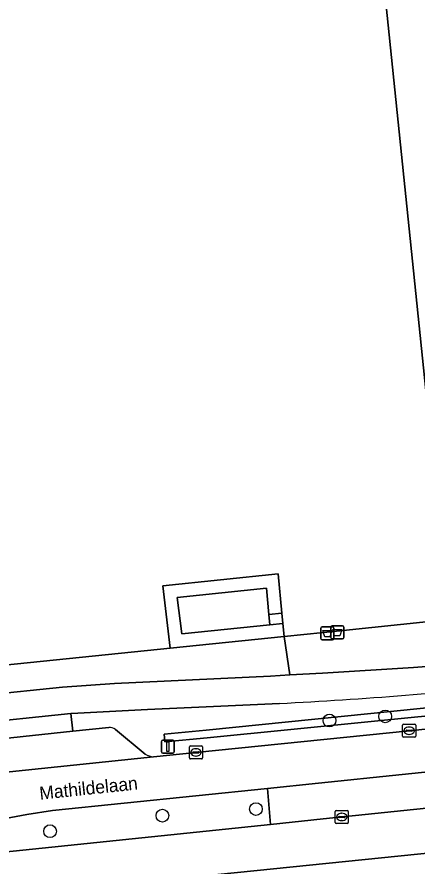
# Model space of a CAD drawing. Extents: x 160675 to 161153, y 383241 to 383714.
# Drawn here: x 161064.7 to 161095.4, y 383570 to 383635.2 of the extents above; entities that cross this region are included whole.
import ezdxf

# ---------------------------------------------------------------- set-up
doc = ezdxf.new("R2010")
doc.units = 0
for name, color, linetype in [('IMGEO_Afvalbak', 7, 'Continuous'), ('IMGEO_Berm_groen', 7, 'Continuous'), ('IMGEO_Boom', 7, 'Continuous'), ('IMGEO_Fietspad_gesloten', 7, 'Continuous'), ('IMGEO_Groenvoorziening', 7, 'Continuous'), ('IMGEO_Haag', 7, 'Continuous'), ('IMGEO_Kolk', 7, 'Continuous'), ('IMGEO_Lichtmast', 7, 'Continuous'), ('IMGEO_Openbare_ruimte_label', 7, 'Continuous'), ('IMGEO_OVBaan_gesloten', 7, 'Continuous'), ('IMGEO_Pand', 7, 'Continuous'), ('IMGEO_Parkeervlak_open', 7, 'Continuous'), ('IMGEO_Rijbaan_lokaal_gesloten', 7, 'Continuous'), ('IMGEO_Voetpad_open', 7, 'Continuous')]:
    doc.layers.add(name, color=color, linetype=linetype)

msp = doc.modelspace()

# ---------------------------------------------------------------- linework, layer by layer
at = {"layer": 'IMGEO_Afvalbak'}
for p, q in [((161088.02, 383587.528), (161088.02, 383588.328)), ((161088.02, 383588.328), (161088.02, 383587.528)), ((161088.12, 383588.428), (161088.91, 383588.428)), ((161088.91, 383588.428), (161088.12, 383588.428)), ((161088.785, 383587.603), (161088.785, 383588.403)), ((161088.785, 383588.403), (161088.785, 383587.603)), ((161088.885, 383588.503), (161089.675, 383588.503)), ((161089.675, 383588.503), (161088.885, 383588.503)), ((161089.01, 383588.328), (161089.01, 383587.528)), ((161089.01, 383587.528), (161089.01, 383588.328)), ((161089.775, 383588.403), (161089.775, 383587.603)), ((161089.775, 383587.603), (161089.775, 383588.403)), ((161088.91, 383587.428), (161088.12, 383587.428)), ((161088.12, 383587.428), (161088.91, 383587.428)), ((161089.675, 383587.503), (161088.885, 383587.503)), ((161088.885, 383587.503), (161089.675, 383587.503))]:
    msp.add_line(p, q, dxfattribs=at)
for points in [[(161088.163, 383588.142), (161088.867, 383588.142), (161088.718, 383587.672), (161088.312, 383587.672), (161088.163, 383588.142)], [(161088.928, 383588.217), (161089.632, 383588.217), (161089.483, 383587.747), (161089.077, 383587.747), (161088.928, 383588.217)]]:
    msp.add_lwpolyline(points, dxfattribs=at)
for centre, start, end in [((161088.12, 383588.328), 90, 180), ((161088.12, 383588.328), 90, 180), ((161088.885, 383588.403), 90, 180), ((161088.885, 383588.403), 90, 180), ((161088.91, 383588.328), 0, 90), ((161088.91, 383588.328), 360, 90), ((161089.675, 383588.403), 0, 90), ((161089.675, 383588.403), 360, 90), ((161088.12, 383587.528), 180, 270), ((161088.12, 383587.528), 180, 270), ((161088.885, 383587.603), 180, 270), ((161088.885, 383587.603), 180, 270), ((161088.91, 383587.528), 270, 0), ((161088.91, 383587.528), 270, 0), ((161089.675, 383587.603), 270, 0), ((161089.675, 383587.603), 270, 0)]:
    msp.add_arc(centre, 0.1, start, end, dxfattribs=at)
at = {"layer": 'IMGEO_Berm_groen'}
msp.add_lwpolyline([(161124.987, 383585.136), (161125.009, 383584.82), (161125.04, 383584.459), (161079.275, 383579.914), (161076.031, 383579.618), (161075.981, 383580.2), (161079.215, 383580.51)], close=True, dxfattribs=at)
for points in [[(161075.158, 383578.46), (161078.421, 383578.799), (161094.799, 383580.465), (161109.18, 383581.972), (161118.029, 383582.893)], [(161084.836, 383582.551), (161074.699, 383582.085), (161068.858, 383581.784), (161068.814, 383581.779), (161068.959, 383580.428), (161071.725, 383580.703)], [(161072.24, 383580.562), (161074.519, 383578.674)], [(161034.895, 383568.454), (161014.99, 383566.38), (161015.019, 383566.144), (161038.417, 383568.551), (161084.138, 383573.282), (161083.912, 383576.034)], [(161083.912, 383576.034), (161067.416, 383574.334), (161065.429, 383574.038), (161038.862, 383569.063)]]:
    msp.add_lwpolyline(points, dxfattribs=at)
for centre, radius, start, end in [((161064.198, 383969.052), 387.052, 273.05651, 275.92633), ((161071.809, 383580), 0.708, 52.55151, 96.82532), ((161075.378, 383580.179), 1.733, 240.27398, 262.6948)]:
    msp.add_arc(centre, radius, start, end, dxfattribs=at)
at = {"layer": 'IMGEO_Boom'}
for centre in [(161088.68, 383581.248), (161092.956, 383581.559), (161083.032, 383574.453), (161075.85, 383573.951), (161067.224, 383572.759)]:
    msp.add_circle(centre, 0.489, dxfattribs=at)
at = {"layer": 'IMGEO_Fietspad_gesloten'}
for points in [[(161120.919, 383585.807), (161124.393, 383586.061), (161124.031, 383588.251), (161097.14, 383585.472), (161095.135, 383585.325), (161088.148, 383584.88), (161085.622, 383584.741), (161084.155, 383584.661), (161072.168, 383584.096), (161068.177, 383583.808), (161062.195, 383583.186)], [(161057.592, 383580.363), (161060.766, 383580.951), (161060.938, 383580.969), (161068.814, 383581.779), (161068.858, 383581.784), (161074.699, 383582.085), (161084.836, 383582.551)]]:
    msp.add_lwpolyline(points, dxfattribs=at)
msp.add_arc((161064.198, 383969.052), 387.052, 273.05651, 275.92633, dxfattribs=at)
at = {"layer": 'IMGEO_Groenvoorziening'}
msp.add_lwpolyline([(161125.04, 383584.459), (161125.009, 383584.82), (161124.987, 383585.136), (161079.215, 383580.51), (161075.981, 383580.2), (161076.031, 383579.618), (161079.275, 383579.914)], close=True, dxfattribs=at)
at = {"layer": 'IMGEO_Haag'}
msp.add_lwpolyline([(161125.04, 383584.459), (161125.009, 383584.82), (161124.987, 383585.136), (161079.215, 383580.51), (161075.981, 383580.2), (161076.031, 383579.618), (161079.275, 383579.914)], close=True, dxfattribs=at)
at = {"layer": 'IMGEO_Kolk'}
for p, q in [((161094.298, 383580.039), (161094.298, 383580.891)), ((161094.373, 383580.965), (161095.225, 383580.965)), ((161095.299, 383580.891), (161095.299, 383580.039)), ((161094.557, 383580.459), (161094.557, 383580.471)), ((161094.995, 383580.422), (161094.597, 383580.422)), ((161094.6, 383580.508), (161094.998, 383580.508)), ((161094.809, 383580.185), (161094.784, 383580.185)), ((161094.786, 383580.745), (161094.811, 383580.745)), ((161095.041, 383580.471), (161095.041, 383580.459)), ((161095.225, 383579.965), (161094.373, 383579.965)), ((161077.92, 383578.373), (161077.92, 383579.225)), ((161077.995, 383579.299), (161078.847, 383579.299)), ((161078.222, 383578.842), (161078.62, 383578.842)), ((161078.408, 383579.079), (161078.433, 383579.079)), ((161078.921, 383579.225), (161078.921, 383578.373)), ((161078.847, 383578.299), (161077.995, 383578.299)), ((161078.179, 383578.793), (161078.179, 383578.805)), ((161078.617, 383578.756), (161078.219, 383578.756)), ((161078.431, 383578.519), (161078.406, 383578.519)), ((161078.663, 383578.805), (161078.663, 383578.793)), ((161089.123, 383573.425), (161089.123, 383574.277)), ((161089.198, 383574.351), (161090.05, 383574.351)), ((161090.124, 383574.277), (161090.124, 383573.425)), ((161089.382, 383573.845), (161089.382, 383573.857)), ((161089.82, 383573.808), (161089.422, 383573.808)), ((161089.425, 383573.894), (161089.823, 383573.894)), ((161089.611, 383574.131), (161089.636, 383574.131)), ((161089.866, 383573.857), (161089.866, 383573.845)), ((161090.05, 383573.351), (161089.198, 383573.351)), ((161089.634, 383573.571), (161089.609, 383573.571))]:
    msp.add_line(p, q, dxfattribs=at)
for points in [[(161094.298, 383580.039), (161094.298, 383580.891)], [(161094.373, 383580.965), (161095.225, 383580.965)], [(161095.299, 383580.891), (161095.299, 383580.039)], [(161095.225, 383579.965), (161094.373, 383579.965)], [(161077.92, 383578.373), (161077.92, 383579.225)], [(161077.995, 383579.299), (161078.847, 383579.299)], [(161078.921, 383579.225), (161078.921, 383578.373)], [(161078.847, 383578.299), (161077.995, 383578.299)], [(161089.123, 383573.425), (161089.123, 383574.277)], [(161089.198, 383574.351), (161090.05, 383574.351)], [(161090.124, 383574.277), (161090.124, 383573.425)], [(161090.05, 383573.351), (161089.198, 383573.351)]]:
    msp.add_lwpolyline(points, dxfattribs=at)
for centre, radius, start, end in [((161094.375, 383580.889), 0.0765, 91.55205, 178.44795), ((161094.375, 383580.889), 0.0765, 91.55205, 178.44795), ((161095.223, 383580.889), 0.0765, 1.55205, 88.44795), ((161095.223, 383580.889), 0.0765, 1.55205, 88.44795), ((161094.597, 383580.468), 0.0403, 85.87752, 175.75265), ((161094.594, 383580.458), 0.0366, 178.93798, 274.71019), ((161094.998, 383580.465), 0.043, 264.86636, 352.45326), ((161095.002, 383580.47), 0.0386, 1.73085, 96.63898), ((161094.375, 383580.041), 0.0765, 181.55205, 268.44795), ((161094.375, 383580.041), 0.0765, 181.55205, 268.44795), ((161095.223, 383580.041), 0.0765, 271.55205, 358.44795), ((161095.223, 383580.041), 0.0765, 271.55205, 358.44795), ((161077.997, 383579.223), 0.0765, 91.55205, 178.44795), ((161077.997, 383579.223), 0.0765, 91.55205, 178.44795), ((161078.219, 383578.802), 0.0403, 85.87752, 175.75265), ((161078.624, 383578.804), 0.0386, 1.73085, 96.63898), ((161078.845, 383579.223), 0.0765, 1.55205, 88.44795), ((161078.845, 383579.223), 0.0765, 1.55205, 88.44795), ((161077.997, 383578.375), 0.0765, 181.55205, 268.44795), ((161077.997, 383578.375), 0.0765, 181.55205, 268.44795), ((161078.216, 383578.792), 0.0366, 178.93798, 274.71019), ((161078.62, 383578.799), 0.043, 264.86636, 352.45326), ((161078.845, 383578.375), 0.0765, 271.55205, 358.44795), ((161078.845, 383578.375), 0.0765, 271.55205, 358.44795), ((161089.2, 383574.275), 0.0765, 91.55205, 178.44795), ((161089.2, 383574.275), 0.0765, 91.55205, 178.44795), ((161090.048, 383574.275), 0.0765, 1.55205, 88.44795), ((161090.048, 383574.275), 0.0765, 1.55205, 88.44795), ((161089.422, 383573.854), 0.0403, 85.87752, 175.75265), ((161089.419, 383573.844), 0.0366, 178.93798, 274.71019), ((161089.823, 383573.851), 0.043, 264.86636, 352.45326), ((161089.827, 383573.856), 0.0386, 1.73085, 96.63898), ((161089.2, 383573.427), 0.0765, 181.55205, 268.44795), ((161089.2, 383573.427), 0.0765, 181.55205, 268.44795), ((161090.048, 383573.427), 0.0765, 271.55205, 358.44795), ((161090.048, 383573.427), 0.0765, 271.55205, 358.44795)]:
    msp.add_arc(centre, radius, start, end, dxfattribs=at)
for centre, major_axis, ratio, start_param, end_param in [((161094.785, 383580.465), (-0.387, 0.002), 0.722429, 4.712389, 7.853982), ((161094.81, 383580.465), (-0.39, 0.002), 0.717154, 1.570796, 4.712389), ((161078.407, 383578.799), (-0.387, 0.002), 0.722429, 4.712389, 7.853982), ((161078.432, 383578.799), (-0.39, 0.002), 0.717154, 1.570796, 4.712389), ((161089.61, 383573.851), (-0.387, 0.002), 0.722429, 4.712389, 7.853982), ((161089.635, 383573.851), (-0.39, 0.002), 0.717154, 1.570796, 4.712389)]:
    msp.add_ellipse(centre, major_axis=major_axis, ratio=ratio, start_param=start_param, end_param=end_param, dxfattribs=at)
at = {"layer": 'IMGEO_Lichtmast'}
for p, q in [((161075.77, 383578.842), (161075.77, 383579.642)), ((161075.77, 383579.642), (161075.77, 383578.842)), ((161075.87, 383579.742), (161076.66, 383579.742)), ((161076.66, 383579.742), (161075.87, 383579.742)), ((161076.76, 383579.642), (161076.76, 383578.842)), ((161076.76, 383578.842), (161076.76, 383579.642)), ((161076.66, 383578.742), (161075.87, 383578.742)), ((161075.87, 383578.742), (161076.66, 383578.742))]:
    msp.add_line(p, q, dxfattribs=at)
msp.add_lwpolyline([(161076.19, 383579.617), (161076.34, 383579.617), (161076.34, 383578.867), (161076.19, 383578.867), (161076.19, 383579.617)], dxfattribs=at)
for centre, start, end in [((161075.87, 383579.642), 90, 180), ((161075.87, 383579.642), 90, 180), ((161076.66, 383579.642), 0, 90), ((161076.66, 383579.642), 360, 90), ((161075.87, 383578.842), 180, 270), ((161075.87, 383578.842), 180, 270), ((161076.66, 383578.842), 270, 0), ((161076.66, 383578.842), 270, 0)]:
    msp.add_arc(centre, 0.1, start, end, dxfattribs=at)
at = {"layer": 'IMGEO_OVBaan_gesloten'}
msp.add_lwpolyline([(161099.72, 383571.421), (161128.738, 383574.467), (161128.396, 383577.816), (161127.033, 383577.671), (161125.413, 383577.499), (161107.04, 383575.646), (161088.192, 383573.701), (161084.138, 383573.282), (161038.417, 383568.551), (161015.019, 383566.144), (161015.035, 383565.999), (161015.167, 383562.758), (161045.124, 383565.881)], close=True, dxfattribs=at)
msp.add_lwpolyline([(161129.136, 383570.809), (161128.738, 383574.467), (161099.72, 383571.421), (161045.124, 383565.881), (161015.167, 383562.758), (161015.36, 383559.547), (161128.627, 383571.185)], dxfattribs=at)
at = {"layer": 'IMGEO_Pand'}
for points in [[(161126.246, 383601.922), (161127.726, 383601.955), (161127.701, 383603.071), (161127.441, 383604.134), (161125.936, 383607.995), (161124.848, 383610.787), (161109.653, 383649.767), (161104.111, 383663.984), (161093.866, 383662.93), (161090.454, 383662.579), (161090.629, 383660.888), (161090.467, 383660.87), (161096.92, 383598.37), (161097.8, 383598.45), (161097.706, 383599.338), (161104.472, 383600.076), (161105.209, 383592.833), (161124.609, 383598.054), (161124.448, 383598.436)], [(161027.74, 383581.8), (161076.456, 383586.789), (161075.89, 383591.57), (161084.73, 383592.49), (161085.023, 383589.483), (161085.1, 383588.687), (161085.197, 383587.691), (161089.735, 383588.159), (161096.343, 383588.84), (161099.422, 383589.166), (161099.226, 383591.056), (161103.493, 383591.497), (161102.865, 383597.667), (161097.94, 383597.13), (161097.8, 383598.45), (161096.92, 383598.37), (161090.467, 383660.87), (161085.69, 383660.33), (161085.53, 383662.01), (161003.438, 383653.613)]]:
    msp.add_lwpolyline(points, dxfattribs=at)
at = {"layer": 'IMGEO_Parkeervlak_open'}
for points in [[(161071.725, 383580.703), (161068.959, 383580.428), (161061.08, 383579.583), (161058.487, 383579.368)], [(161074.519, 383578.674), (161072.24, 383580.562)], [(161055.488, 383576.424), (161075.158, 383578.46)]]:
    msp.add_lwpolyline(points, dxfattribs=at)
for centre, radius, start, end in [((161071.809, 383580), 0.708, 52.55151, 96.82532), ((161075.378, 383580.179), 1.733, 240.27398, 262.6948)]:
    msp.add_arc(centre, radius, start, end, dxfattribs=at)
at = {"layer": 'IMGEO_Rijbaan_lokaal_gesloten'}
for points in [[(161118.029, 383582.893), (161109.18, 383581.972), (161094.799, 383580.465), (161078.421, 383578.799), (161075.158, 383578.46), (161055.488, 383576.424), (161046.311, 383575.497), (161031.914, 383573.995), (161017.538, 383572.511), (161014.164, 383572.163), (161014.554, 383568.898), (161014.99, 383566.38), (161034.895, 383568.454)], [(161083.912, 383576.034), (161087.833, 383576.438), (161126.393, 383580.429)], [(161038.862, 383569.063), (161065.429, 383574.038), (161067.416, 383574.334), (161083.912, 383576.034)]]:
    msp.add_lwpolyline(points, dxfattribs=at)
at = {"layer": 'IMGEO_Voetpad_open'}
for points in [[(161062.195, 383583.186), (161068.177, 383583.808), (161072.168, 383584.096), (161084.155, 383584.661), (161085.622, 383584.741), (161085.197, 383587.691), (161076.456, 383586.789), (161027.74, 383581.8), (161018.91, 383580.89), (161009.37, 383579.88), (161007.86, 383579.72), (161006.305, 383579.479), (161005.816, 383583.932), (161004.319, 383598.403)], [(161128.698, 383590.188), (161131.185, 383591.861), (161131.736, 383592.39), (161132.591, 383593.336), (161129.716, 383593.455), (161105.374, 383590.924), (161105.316, 383591.598), (161103.493, 383591.497), (161099.226, 383591.056), (161099.422, 383589.166), (161096.343, 383588.84), (161089.735, 383588.159), (161085.197, 383587.691), (161085.622, 383584.741), (161088.148, 383584.88), (161095.135, 383585.325), (161097.14, 383585.472), (161124.031, 383588.251), (161124.042, 383588.252)], [(161126.393, 383580.429), (161087.833, 383576.438), (161083.912, 383576.034), (161084.138, 383573.282), (161088.192, 383573.701), (161107.04, 383575.646), (161125.413, 383577.499), (161127.033, 383577.671)]]:
    msp.add_lwpolyline(points, dxfattribs=at)
for points in [[(161077.349, 383587.887), (161076.989, 383590.68), (161083.84, 383591.393), (161084.027, 383589.381), (161085.023, 383589.483), (161084.73, 383592.49), (161075.89, 383591.57), (161076.456, 383586.789), (161085.197, 383587.691), (161085.1, 383588.687), (161084.101, 383588.584)], [(161083.84, 383591.393), (161076.989, 383590.68), (161077.349, 383587.887), (161084.101, 383588.584), (161084.027, 383589.381)], [(161084.101, 383588.584), (161085.1, 383588.687), (161085.023, 383589.483), (161084.027, 383589.381)], [(161068.814, 383581.779), (161060.938, 383580.969), (161061.08, 383579.583), (161068.959, 383580.428)]]:
    msp.add_lwpolyline(points, close=True, dxfattribs=at)

# ---------------------------------------------------------------- texts
at = {"layer": 'IMGEO_Openbare_ruimte_label'}
msp.add_text('Mathildelaan', height=1, rotation=6.02399, dxfattribs=at).set_placement((161066.454, 383575.169))

doc.saveas('drawing.dxf')
